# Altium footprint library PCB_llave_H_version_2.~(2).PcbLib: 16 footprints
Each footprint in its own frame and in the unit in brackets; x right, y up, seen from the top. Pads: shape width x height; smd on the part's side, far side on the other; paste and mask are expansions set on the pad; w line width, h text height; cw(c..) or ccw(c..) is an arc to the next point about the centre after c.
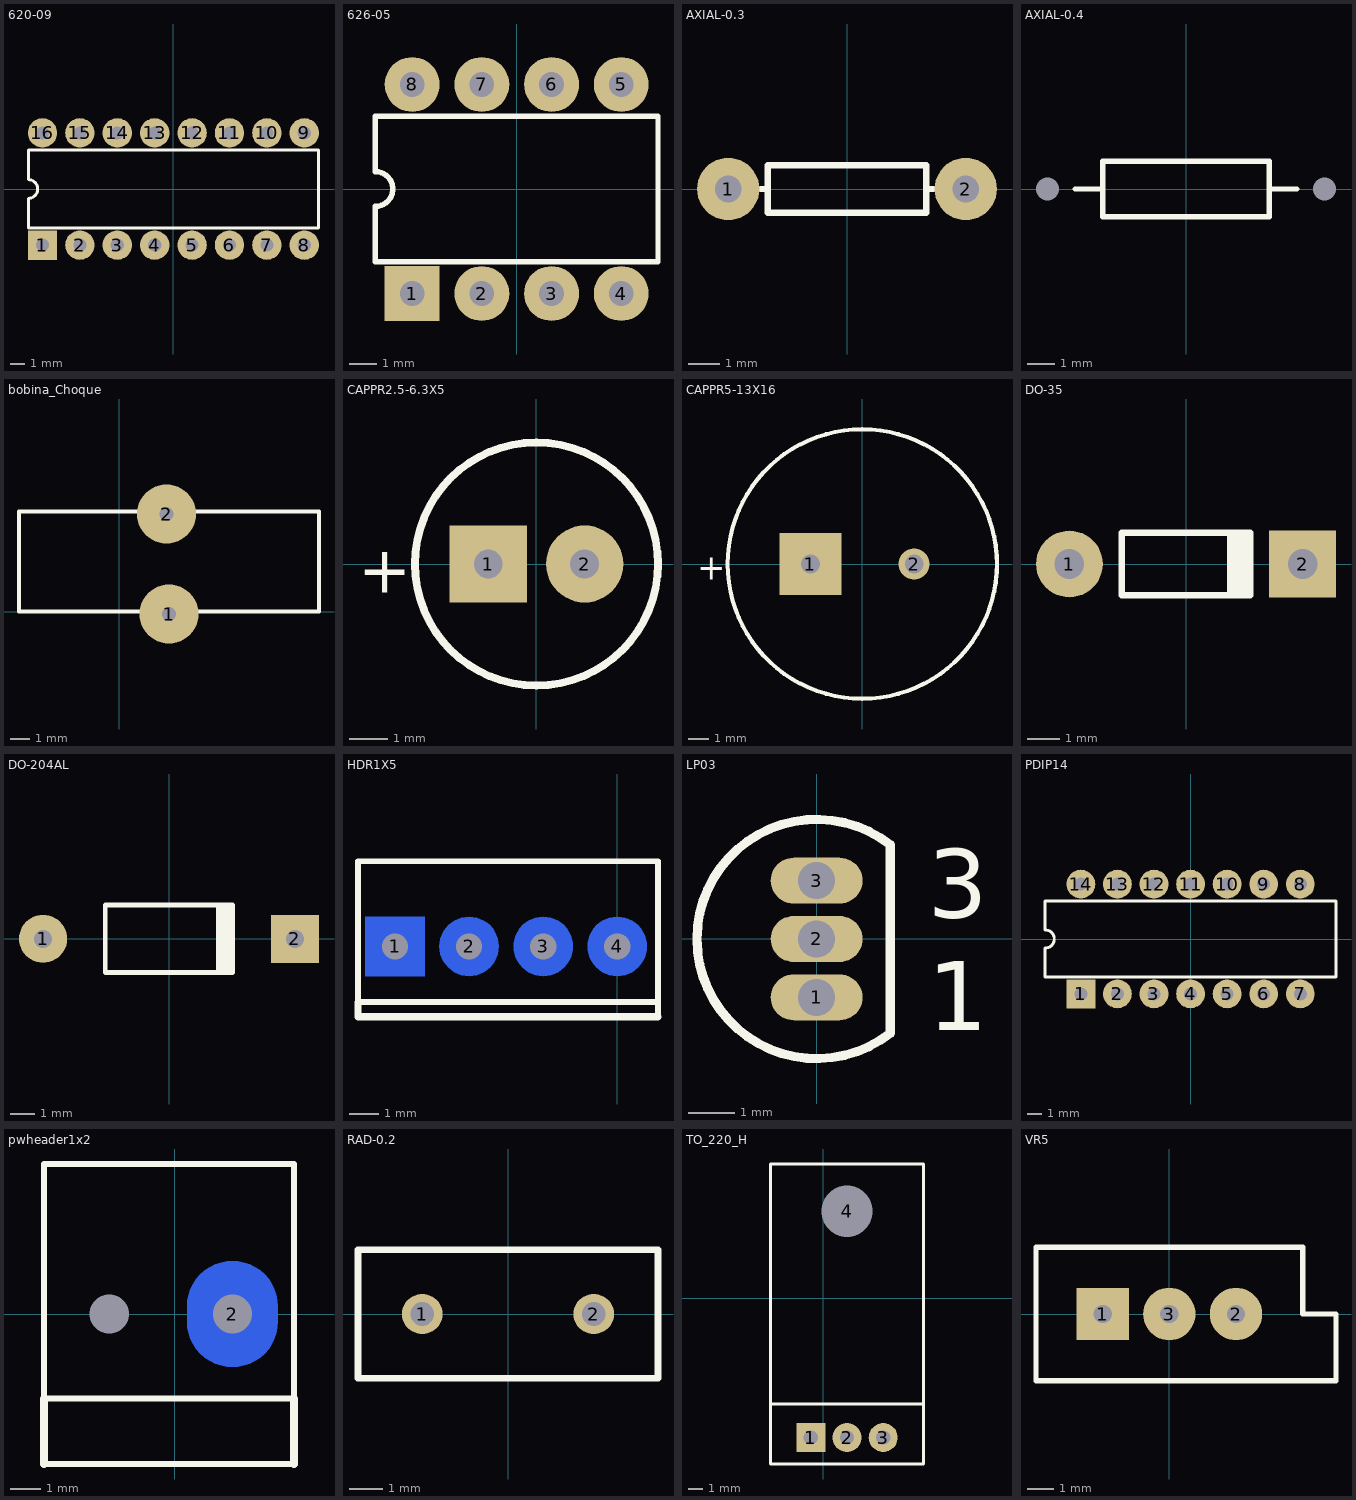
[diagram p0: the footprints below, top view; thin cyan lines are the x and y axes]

## 620-09 [mm] "DIP; 16 Leads; Row Spacing 7.62 mm; Pitch 2.54 mm"
height 4.19
pads (16):
  rect 2x2 hole 0.9: 1(-8.89,-3.81)
  round 2 hole 0.9: 2(-6.35,-3.81) 3(-3.81,-3.81) 4(-1.27,-3.81) 5(1.27,-3.81) 6(3.81,-3.81) 7(6.35,-3.81) 8(8.89,-3.81) 9(8.89,3.81) 10(6.35,3.81) 11(3.81,3.81) 12(1.27,3.81) 13(-1.27,3.81) 14(-3.81,3.81) 15(-6.35,3.81) 16(-8.89,3.81)
Top Overlay:
  lines w0.2: -9.85,-2.65 -9.85,-0.635 ccw(c-9.85,0) -9.85,0.635 -9.85,2.65 9.85,2.65 9.85,-2.65 -9.85,-2.65

## 626-05 [mm] "DIP; 8 Leads; Row Spacing 7.62 mm; Pitch 2.54 mm"
height 4.45
pads (8):
  rect 2x2 hole 0.9: 1(-3.81,-3.81)
  round 2 hole 0.9: 2(-1.27,-3.81) 3(1.27,-3.81) 4(3.81,-3.81) 5(3.81,3.81) 6(1.27,3.81) 7(-1.27,3.81) 8(-3.81,3.81)
Top Overlay:
  lines w0.2: -5.15,-2.65 5.15,-2.65 5.15,2.65 -5.15,2.65 -5.15,0.635 cw(c-5.15,0) -5.15,-0.635 -5.15,-2.65

## AXIAL-0.3 [mm] "Resistor; 2 Leads"
height 1.524
pads (2):
  round 2 hole 0.85: 1(-3.81,0) 2(3.81,0)
Top Overlay:
  lines w0.2: -2.769,0 -2.54,0 ; 2.769,0 2.54,0 ; 2.54,0 2.54,0.762 -2.54,0.762 -2.54,-0.762 2.54,-0.762 2.54,0

## AXIAL-0.4 [mm] "Resistor; 2 Leads"
height 2.032
pads (2):
  round 0 / inner round 0 / far side round 2 hole 0.85: 1(-5.08,0) 2(5.08,0)
Top Overlay:
  lines w0.2: -4.064,0 -3.048,0 ; 3.048,0 4.064,0 ; -3.048,-1.016 3.048,-1.016 3.048,1.016 -3.048,1.016 -3.048,-1.016

## bobina_Choque [mm]
pads (2):
  round 3 hole 0.7: 1(2.54,-0.127) 2(2.413,4.953)
Top Overlay:
  lines w0.2: -5.08,0 10.16,0 10.16,5.08 -5.08,5.08 -5.08,0

## CAPPR2.5-6.3X5 [mm] "Capacitor, Electrolytic, Radial; Body 6.3 x 5 mm (Dia.xH typ); Pin Spacing 2.5 mm (typ)"
height 6
pads (2):
  rect 2x2 hole 0.75: 1(-1.25,0)
  round 2 hole 0.75: 2(1.25,0)
Top Overlay:
  circle w0.2: c0,0 r3.15
  text "+" at -4.625,-0.75 h1.2

## CAPPR5-13X16 [mm] "Capacitor, Electrolytic, Radial; Body 13 x 16 mm (Dia.xH typ); Pin Spacing 5 mm (typ)"
height 18
pads (2):
  rect 3x3 hole 0.9: 1(-2.5,0)
  round 1.5 hole 0.9: 2(2.5,0)
Top Overlay:
  circle w0.2: c0,0 r6.5
  text "+" at -7.975,-0.75 h1.2

## DO-35 [mm] "Diode, Axial; Body 3.8 x 1.9 mm (LxDia. max), Lead Dia. 0.53 mm (max)"
height 1.9
pads (2):
  round 2.032 hole 0.9: 1(-3.55,0)
  rect 2.032x2.032 hole 0.9: 2(3.55,0)
Top Overlay:
  rectangle: 1.25,-0.95 2.05,0.95
  lines w0.2: 1.95,-0.95 -1.95,-0.95 -1.95,0.95 1.95,0.95

## DO-204AL [mm] "Diode, Axial; Body 5.2 x 2.7 mm (LxDia. max), Lead Dia. 0.86 mm (max)"
height 2.7
pads (2):
  round 2 hole 0.75: 1(-5.23,0)
  rect 2x2 hole 0.75: 2(5.23,0)
Top Overlay:
  rectangle: 1.95,-1.413 2.75,1.387
  lines w0.2: 2.65,-1.4 -2.65,-1.4 -2.65,1.4 2.65,1.4

## HDR1X5 [mil]
pads (4):
  rect 80x80 smd far side: 1(-300,300)
  round 80 smd far side: 2(-200,300) 3(-100,300) 4(0,300)
Top Overlay:
  lines w7.87: 55,205 55,415 -350,415 -350,225 55,225
  lines w10: -350,225 -350,205 55,205

## LP03 [mm] "TO, Flat Index; 3 In-Line, Axial Leads; Body Dia. 4.8mm; Leads 0.56 x 0.41 mm (max)"
height 5.34
pads (3):
  oval 2x1 hole 0.8: 1(0,-1.27) 2(0,0) 3(0,1.27)
Top Overlay:
  lines w0.2: 1.601,-2.049 cw(c0,0) 1.601,2.049 ; 1.6,-1.99 1.6,1.99
  text "1" at 2.421,-1.979 h1.5
  text "3" at 2.421,0.467 h1.5

## PDIP14 [mm] "DIP; 14 Leads; Row Spacing 7.62 mm; Pitch 2.54 mm"
height 5.33
pads (14):
  rect 2x2 hole 0.9: 1(-7.62,-3.81)
  round 2 hole 0.9: 2(-5.08,-3.81) 3(-2.54,-3.81) 4(0,-3.81) 5(2.54,-3.81) 6(5.08,-3.81) 7(7.62,-3.81) 8(7.62,3.81) 9(5.08,3.81) 10(2.54,3.81) 11(0,3.81) 12(-2.54,3.81) 13(-5.08,3.81) 14(-7.62,3.81)
Top Overlay:
  lines w0.2: -10.1,-2.65 10.1,-2.65 10.1,2.65 -10.1,2.65 -10.1,0.635 cw(c-10.1,0) -10.1,-0.635 -10.1,-2.65

## pwheader1x2 [mm]
pads (2):
  round 0 / inner round 0 / far side rect 3x3.5 hole 1.3: 1(-2.159,0)
  oval 3x3.5 smd far side: 2(1.905,0)
Top Overlay:
  lines w0.2: -4.318,-4.953 3.937,-4.953 ; -4.318,-2.794 3.937,-2.794 3.937,4.953 -4.318,4.953 -4.318,-2.794
  lines w0.254: -4.318,-4.953 -4.318,-2.794 ; 3.937,-4.953 3.937,-2.794

## RAD-0.2 [mm] "Jumper Wire; 2 Leads"
pads (2):
  round 1.2 hole 0.7: 1(-2.54,0) 2(2.54,0)
Top Overlay:
  lines w0.2: -4.445,-1.905 -4.445,1.905 4.445,1.905 4.445,-1.905 -4.445,-1.905

## TO_220_H [mil] "to-220 horizontal"
pads (4):
  rect 80x80 hole 39.37: 1(-35,-385)
  round 80 hole 39.37: 2(65,-385) 3(165,-385)
  round 80 hole 141.73: 4(65,240)
Top Overlay:
  lines w7.87: -145.63,-292.48 275.63,-292.48 ; -145.63,-457.83 275.63,-457.83 275.63,370 -145.63,370 -145.63,-457.83

## VR5 [mm] "Potentiometer; 3 Leads"
pads (3):
  rect 2x2 hole 0.7: 1(-2.54,0)
  round 2 hole 0.7: 2(2.54,0) 3(0,0)
Top Overlay:
  lines w0.2: -5.08,-2.54 6.35,-2.54 6.35,0 5.08,0 5.08,2.54 -5.08,2.54 -5.08,-2.54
